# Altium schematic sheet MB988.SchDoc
size A3; Revision: B.2
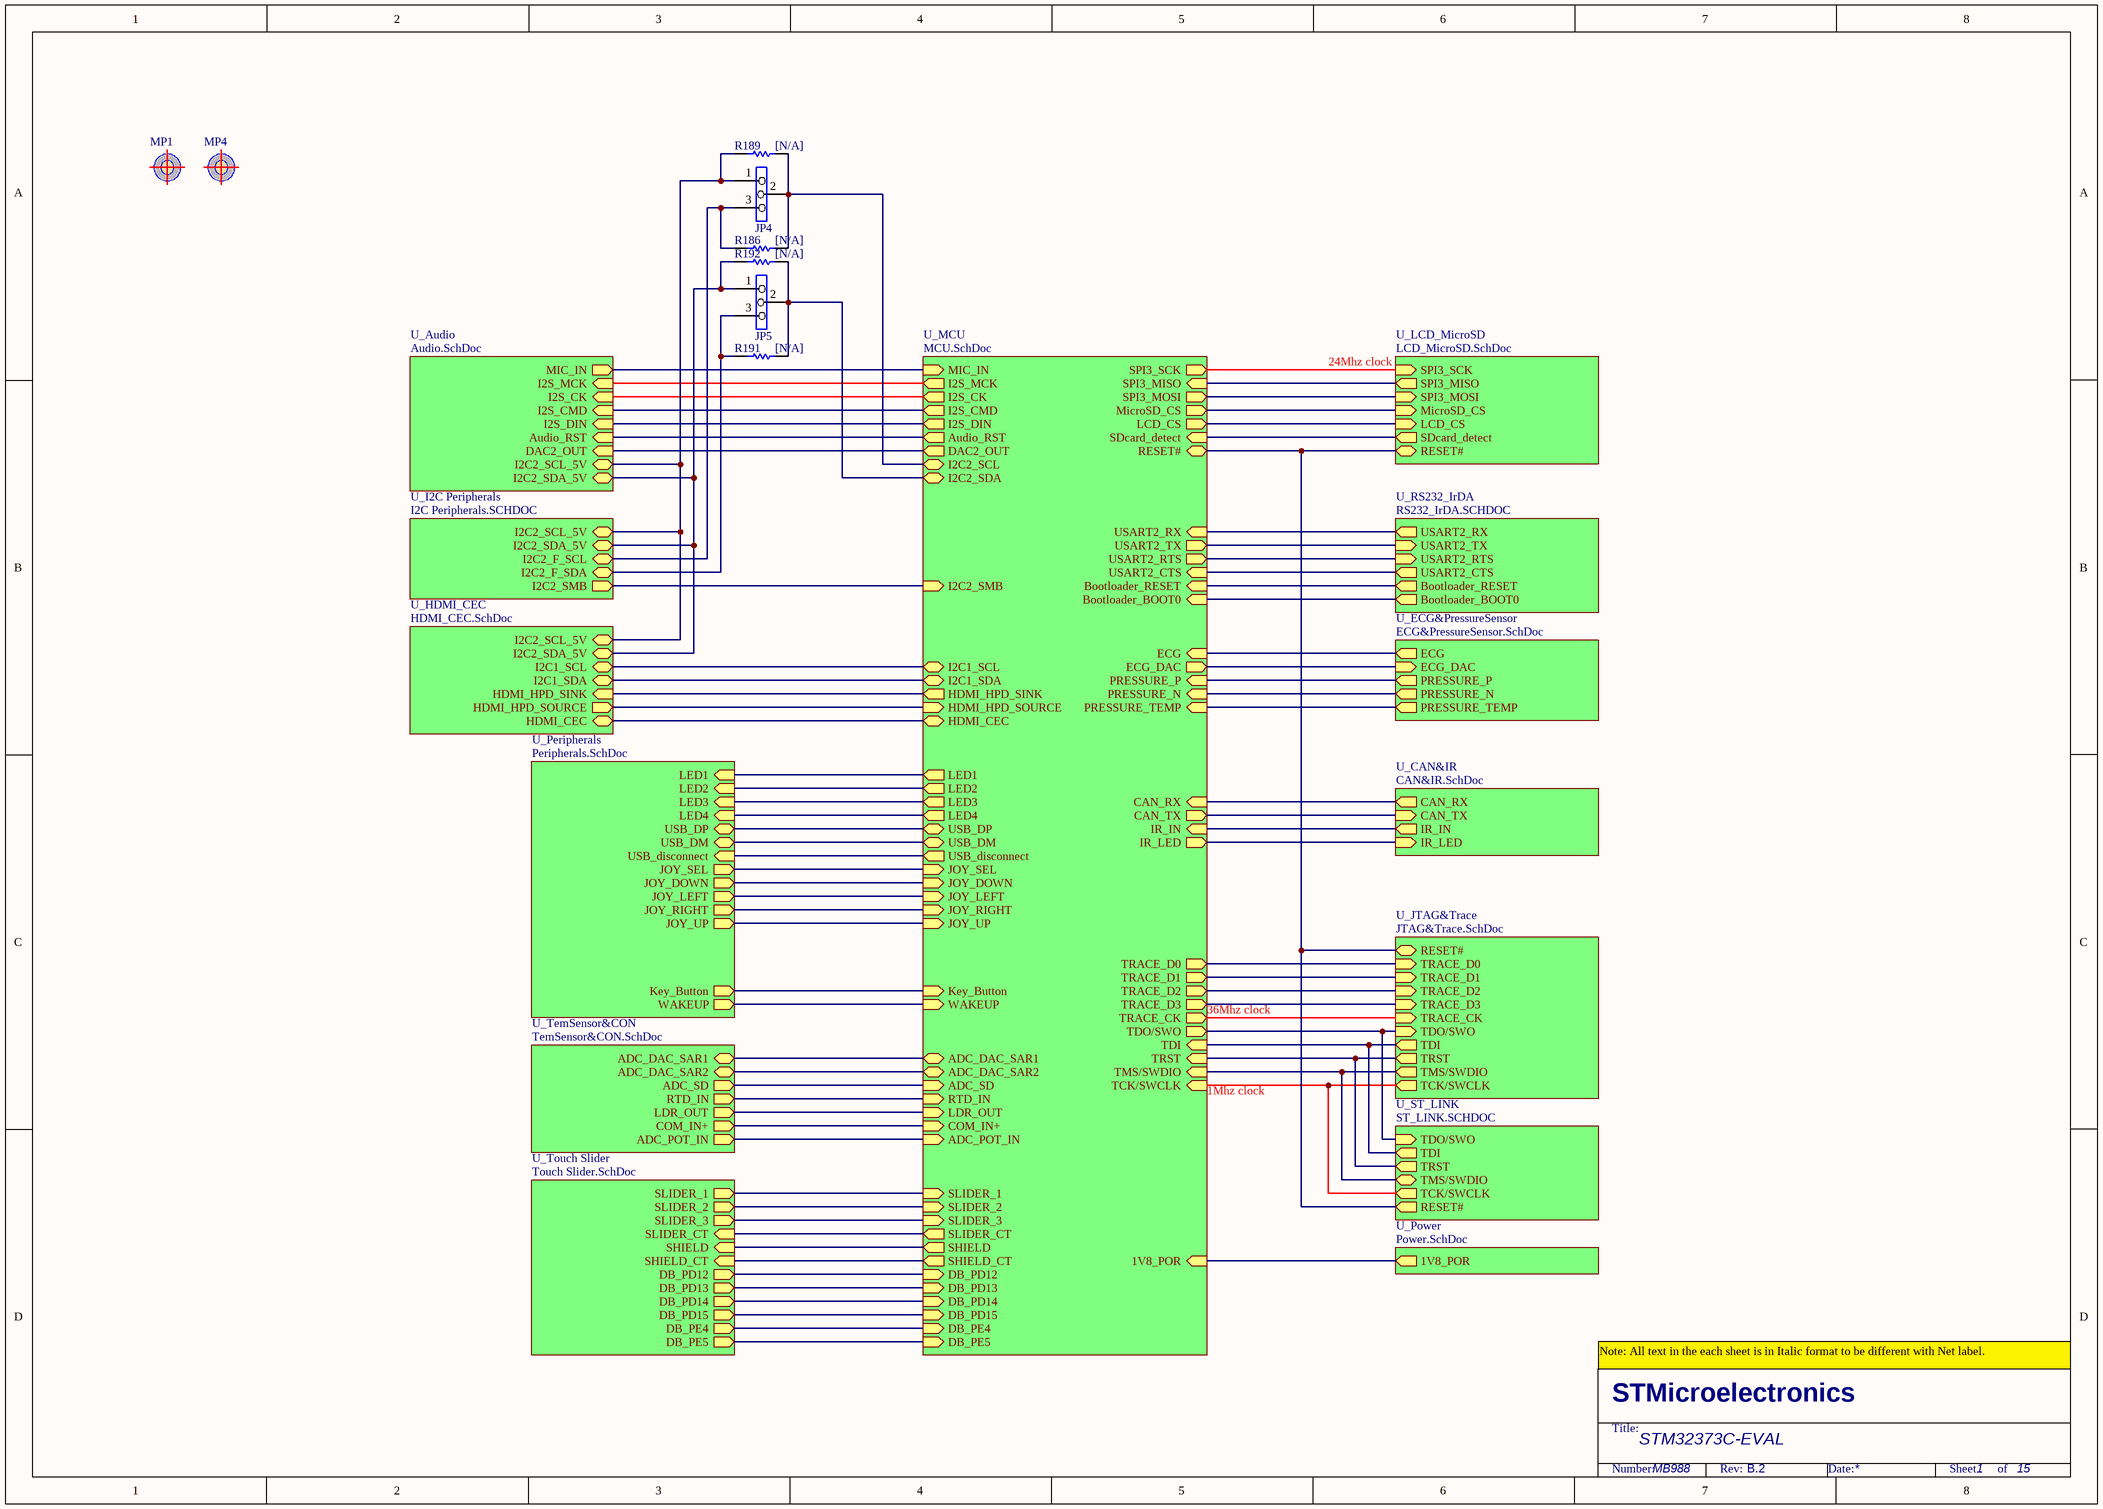
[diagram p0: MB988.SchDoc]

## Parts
JP4  (no value)  [SIP3]
JP5  (no value)  [SIP3]
MP1  (no value)  [markpoint_1.0]
MP4  (no value)  [markpoint_1.0]
R186  [N/A]  [0603R]
R189  [N/A]  [0603R]
R191  [N/A]  [0603R]
R192  [N/A]  [0603R]

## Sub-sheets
U_Audio = Audio.SchDoc: I2S_CMD (in), I2S_DIN (in), I2S_CK (in), I2C2_SCL_5V (bidir), I2C2_SDA_5V (bidir), Audio_RST (in), I2S_MCK (in), DAC2_OUT (in), MIC_IN (out)
U_CAN&IR = CAN&IR.SchDoc: CAN_TX (in), CAN_RX (out), IR_LED (in), IR_IN (out)
U_ECG&PressureSensor = ECG&PressureSensor.SchDoc: ECG (out), PRESSURE_P (out), PRESSURE_N (out), ECG_DAC (in), PRESSURE_TEMP (out)
U_HDMI_CEC = HDMI_CEC.SchDoc: HDMI_HPD_SINK (in), I2C2_SDA_5V (bidir), I2C2_SCL_5V (bidir), HDMI_CEC (bidir), HDMI_HPD_SOURCE (out), I2C1_SCL (bidir), I2C1_SDA (bidir)
U_I2C Peripherals = I2C Peripherals.SCHDOC: I2C2_SCL_5V (bidir), I2C2_SDA_5V (bidir), I2C2_SMB (out), I2C2_F_SDA (bidir), I2C2_F_SCL (bidir)
U_JTAG&Trace = JTAG&Trace.SchDoc: TDI (out), RESET# (bidir), TRACE_D3 (in), TRACE_D2 (in), TRACE_D1 (in), TRACE_D0 (in), TRACE_CK (in), TRST (out), TMS/SWDIO (out), TCK/SWCLK (out), TDO/SWO (in)
U_LCD_MicroSD = LCD_MicroSD.SchDoc: MicroSD_CS (in), SPI3_SCK (in), SPI3_MOSI (in), LCD_CS (in), SPI3_MISO (out), SDcard_detect (out), RESET# (bidir)
U_MCU = MCU.SchDoc: WAKEUP (in), HDMI_HPD_SOURCE (in), SLIDER_3 (in), ADC_DAC_SAR2 (bidir), USB_DM (bidir), I2C2_SCL (bidir), I2C2_SDA (bidir), TMS/SWDIO (in), TCK/SWCLK (in), TDI (in), MIC_IN (in), COM_IN+ (in), TDO/SWO (out), TRST (in), IR_IN (in), HDMI_CEC (bidir), IR_LED (out), RESET# (bidir), LDR_OUT (in), SLIDER_2 (in), SLIDER_1 (in), USART2_RX (in), USART2_TX (out), USART2_RTS (out), USART2_CTS (in), ECG (in), ADC_SD (in), PRESSURE_N (in), PRESSURE_P (in), SPI3_MOSI (out), SPI3_MISO (in), SPI3_SCK (out), LED4 (out), LED3 (out), LED1 (out), I2S_MCK (out), I2S_CK (out), I2S_CMD (out), LED2 (out), Bootloader_BOOT0 (in), Bootloader_RESET (in), ADC_DAC_SAR1 (bidir), I2S_DIN (out), I2C2_SMB (in), USB_DP (bidir), CAN_RX (in), CAN_TX (out), SLIDER_CT (out), MicroSD_CS (out), TRACE_D0 (out), TRACE_D1 (out), Key_Button (in), JOY_SEL (in), RTD_IN (in), PRESSURE_TEMP (in), JOY_DOWN (in), JOY_LEFT (in), JOY_UP (in), JOY_RIGHT (in), DAC2_OUT (out), TRACE_CK (out), LCD_CS (out), SHIELD (out), TRACE_D2 (out), SHIELD_CT (out), TRACE_D3 (out), HDMI_HPD_SINK (out), Audio_RST (out), SDcard_detect (in), ECG_DAC (out), ADC_POT_IN (in), DB_PD14 (in), DB_PD13 (in), DB_PD12 (in), DB_PD15 (in), 1V8_POR (in), USB_disconnect (out), I2C1_SCL (bidir), I2C1_SDA (bidir), DB_PE4 (in), DB_PE5 (in)
U_Peripherals = Peripherals.SchDoc: LED4 (in), LED3 (in), LED1 (in), LED2 (in), JOY_SEL (out), JOY_DOWN (out), JOY_LEFT (out), JOY_RIGHT (out), JOY_UP (out), USB_DM (bidir), USB_DP (bidir), WAKEUP (out), Key_Button (out), USB_disconnect (in)
U_Power = Power.SchDoc: 1V8_POR (out)
U_RS232_IrDA = RS232_IrDA.SCHDOC: USART2_TX (in), USART2_CTS (out), Bootloader_RESET (out), Bootloader_BOOT0 (out), USART2_RX (out), USART2_RTS (in)
U_ST_LINK = ST_LINK.SCHDOC: TDI (out), TRST (out), TMS/SWDIO (bidir), TCK/SWCLK (out), TDO/SWO (in), RESET# (out)
U_TemSensor&CON = TemSensor&CON.SchDoc: RTD_IN (out), LDR_OUT (out), COM_IN+ (out), ADC_POT_IN (out), ADC_DAC_SAR1 (bidir), ADC_SD (out), ADC_DAC_SAR2 (bidir)
U_Touch Slider = Touch Slider.SchDoc: SLIDER_2 (out), SLIDER_3 (out), SHIELD (in), SHIELD_CT (in), SLIDER_1 (out), DB_PD14 (out), DB_PD13 (out), DB_PD12 (out), SLIDER_CT (in), DB_PD15 (out), DB_PE4 (out), DB_PE5 (out)

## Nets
NetJP4_1: JP4.1 R189.2 ; sheet U_Audio/I2C2_SCL_5V, sheet U_I2C Peripherals/I2C2_SCL_5V, sheet U_HDMI_CEC/I2C2_SCL_5V
NetJP4_2: JP4.2 R186.1 R189.1 ; sheet U_MCU/I2C2_SCL
NetJP4_3: JP4.3 R186.2 ; sheet U_I2C Peripherals/I2C2_F_SCL
NetJP5_1: JP5.1 R192.2 ; sheet U_Audio/I2C2_SDA_5V, sheet U_I2C Peripherals/I2C2_SDA_5V, sheet U_HDMI_CEC/I2C2_SDA_5V
NetJP5_2: JP5.2 R191.1 R192.1 ; sheet U_MCU/I2C2_SDA
NetJP5_3: JP5.3 R191.2 ; sheet U_I2C Peripherals/I2C2_F_SDA
(unnamed): sheet U_MCU/WAKEUP, sheet U_Peripherals/WAKEUP
(unnamed): sheet U_MCU/HDMI_HPD_SOURCE, sheet U_HDMI_CEC/HDMI_HPD_SOURCE  [a separate net that carries the same name]
(unnamed): sheet U_MCU/SLIDER_3, sheet U_Touch Slider/SLIDER_3  [a separate net that carries the same name]
(unnamed): sheet U_MCU/ADC_DAC_SAR2, sheet U_TemSensor&CON/ADC_DAC_SAR2  [a separate net that carries the same name]
(unnamed): sheet U_MCU/USB_DM, sheet U_Peripherals/USB_DM  [a separate net that carries the same name]
(unnamed): sheet U_MCU/TMS/SWDIO, sheet U_JTAG&Trace/TMS/SWDIO, sheet U_ST_LINK/TMS/SWDIO  [a separate net that carries the same name]
(unnamed): sheet U_MCU/TCK/SWCLK, sheet U_JTAG&Trace/TCK/SWCLK, sheet U_ST_LINK/TCK/SWCLK  [a separate net that carries the same name]
(unnamed): sheet U_MCU/TDI, sheet U_JTAG&Trace/TDI, sheet U_ST_LINK/TDI  [a separate net that carries the same name]
(unnamed): sheet U_MCU/MIC_IN, sheet U_Audio/MIC_IN  [a separate net that carries the same name]
(unnamed): sheet U_MCU/COM_IN+, sheet U_TemSensor&CON/COM_IN+  [a separate net that carries the same name]
(unnamed): sheet U_MCU/TDO/SWO, sheet U_JTAG&Trace/TDO/SWO, sheet U_ST_LINK/TDO/SWO  [a separate net that carries the same name]
(unnamed): sheet U_MCU/TRST, sheet U_JTAG&Trace/TRST, sheet U_ST_LINK/TRST  [a separate net that carries the same name]
(unnamed): sheet U_MCU/IR_IN, sheet U_CAN&IR/IR_IN  [a separate net that carries the same name]
(unnamed): sheet U_MCU/HDMI_CEC, sheet U_HDMI_CEC/HDMI_CEC  [a separate net that carries the same name]
(unnamed): sheet U_MCU/IR_LED, sheet U_CAN&IR/IR_LED  [a separate net that carries the same name]
(unnamed): sheet U_MCU/RESET#, sheet U_JTAG&Trace/RESET#, sheet U_ST_LINK/RESET#, sheet U_LCD_MicroSD/RESET#  [a separate net that carries the same name]
(unnamed): sheet U_MCU/LDR_OUT, sheet U_TemSensor&CON/LDR_OUT  [a separate net that carries the same name]
(unnamed): sheet U_MCU/SLIDER_2, sheet U_Touch Slider/SLIDER_2  [a separate net that carries the same name]
(unnamed): sheet U_MCU/SLIDER_1, sheet U_Touch Slider/SLIDER_1  [a separate net that carries the same name]
(unnamed): sheet U_MCU/USART2_RX, sheet U_RS232_IrDA/USART2_RX  [a separate net that carries the same name]
(unnamed): sheet U_MCU/USART2_TX, sheet U_RS232_IrDA/USART2_TX  [a separate net that carries the same name]
(unnamed): sheet U_MCU/USART2_RTS, sheet U_RS232_IrDA/USART2_RTS  [a separate net that carries the same name]
(unnamed): sheet U_MCU/USART2_CTS, sheet U_RS232_IrDA/USART2_CTS  [a separate net that carries the same name]
(unnamed): sheet U_MCU/ECG, sheet U_ECG&PressureSensor/ECG  [a separate net that carries the same name]
(unnamed): sheet U_MCU/ADC_SD, sheet U_TemSensor&CON/ADC_SD  [a separate net that carries the same name]
(unnamed): sheet U_MCU/PRESSURE_N, sheet U_ECG&PressureSensor/PRESSURE_N  [a separate net that carries the same name]
(unnamed): sheet U_MCU/PRESSURE_P, sheet U_ECG&PressureSensor/PRESSURE_P  [a separate net that carries the same name]
(unnamed): sheet U_MCU/SPI3_MOSI, sheet U_LCD_MicroSD/SPI3_MOSI  [a separate net that carries the same name]
(unnamed): sheet U_MCU/SPI3_MISO, sheet U_LCD_MicroSD/SPI3_MISO  [a separate net that carries the same name]
(unnamed): sheet U_MCU/SPI3_SCK, sheet U_LCD_MicroSD/SPI3_SCK  [a separate net that carries the same name]
(unnamed): sheet U_MCU/LED4, sheet U_Peripherals/LED4  [a separate net that carries the same name]
(unnamed): sheet U_MCU/LED3, sheet U_Peripherals/LED3  [a separate net that carries the same name]
(unnamed): sheet U_MCU/LED1, sheet U_Peripherals/LED1  [a separate net that carries the same name]
(unnamed): sheet U_MCU/I2S_MCK, sheet U_Audio/I2S_MCK  [a separate net that carries the same name]
(unnamed): sheet U_MCU/I2S_CK, sheet U_Audio/I2S_CK  [a separate net that carries the same name]
(unnamed): sheet U_MCU/I2S_CMD, sheet U_Audio/I2S_CMD  [a separate net that carries the same name]
(unnamed): sheet U_MCU/LED2, sheet U_Peripherals/LED2  [a separate net that carries the same name]
(unnamed): sheet U_MCU/Bootloader_BOOT0, sheet U_RS232_IrDA/Bootloader_BOOT0  [a separate net that carries the same name]
(unnamed): sheet U_MCU/Bootloader_RESET, sheet U_RS232_IrDA/Bootloader_RESET  [a separate net that carries the same name]
(unnamed): sheet U_MCU/ADC_DAC_SAR1, sheet U_TemSensor&CON/ADC_DAC_SAR1  [a separate net that carries the same name]
(unnamed): sheet U_MCU/I2S_DIN, sheet U_Audio/I2S_DIN  [a separate net that carries the same name]
(unnamed): sheet U_MCU/I2C2_SMB, sheet U_I2C Peripherals/I2C2_SMB  [a separate net that carries the same name]
(unnamed): sheet U_MCU/USB_DP, sheet U_Peripherals/USB_DP  [a separate net that carries the same name]
(unnamed): sheet U_MCU/CAN_RX, sheet U_CAN&IR/CAN_RX  [a separate net that carries the same name]
(unnamed): sheet U_MCU/CAN_TX, sheet U_CAN&IR/CAN_TX  [a separate net that carries the same name]
(unnamed): sheet U_MCU/SLIDER_CT, sheet U_Touch Slider/SLIDER_CT  [a separate net that carries the same name]
(unnamed): sheet U_MCU/MicroSD_CS, sheet U_LCD_MicroSD/MicroSD_CS  [a separate net that carries the same name]
(unnamed): sheet U_MCU/TRACE_D0, sheet U_JTAG&Trace/TRACE_D0  [a separate net that carries the same name]
(unnamed): sheet U_MCU/TRACE_D1, sheet U_JTAG&Trace/TRACE_D1  [a separate net that carries the same name]
(unnamed): sheet U_MCU/Key_Button, sheet U_Peripherals/Key_Button  [a separate net that carries the same name]
(unnamed): sheet U_MCU/JOY_SEL, sheet U_Peripherals/JOY_SEL  [a separate net that carries the same name]
(unnamed): sheet U_MCU/RTD_IN, sheet U_TemSensor&CON/RTD_IN  [a separate net that carries the same name]
(unnamed): sheet U_MCU/PRESSURE_TEMP, sheet U_ECG&PressureSensor/PRESSURE_TEMP  [a separate net that carries the same name]
(unnamed): sheet U_MCU/JOY_DOWN, sheet U_Peripherals/JOY_DOWN  [a separate net that carries the same name]
(unnamed): sheet U_MCU/JOY_LEFT, sheet U_Peripherals/JOY_LEFT  [a separate net that carries the same name]
(unnamed): sheet U_MCU/JOY_UP, sheet U_Peripherals/JOY_UP  [a separate net that carries the same name]
(unnamed): sheet U_MCU/JOY_RIGHT, sheet U_Peripherals/JOY_RIGHT  [a separate net that carries the same name]
(unnamed): sheet U_MCU/DAC2_OUT, sheet U_Audio/DAC2_OUT  [a separate net that carries the same name]
(unnamed): sheet U_MCU/TRACE_CK, sheet U_JTAG&Trace/TRACE_CK  [a separate net that carries the same name]
(unnamed): sheet U_MCU/LCD_CS, sheet U_LCD_MicroSD/LCD_CS  [a separate net that carries the same name]
(unnamed): sheet U_MCU/SHIELD, sheet U_Touch Slider/SHIELD  [a separate net that carries the same name]
(unnamed): sheet U_MCU/TRACE_D2, sheet U_JTAG&Trace/TRACE_D2  [a separate net that carries the same name]
(unnamed): sheet U_MCU/SHIELD_CT, sheet U_Touch Slider/SHIELD_CT  [a separate net that carries the same name]
(unnamed): sheet U_MCU/TRACE_D3, sheet U_JTAG&Trace/TRACE_D3  [a separate net that carries the same name]
(unnamed): sheet U_MCU/HDMI_HPD_SINK, sheet U_HDMI_CEC/HDMI_HPD_SINK  [a separate net that carries the same name]
(unnamed): sheet U_MCU/Audio_RST, sheet U_Audio/Audio_RST  [a separate net that carries the same name]
(unnamed): sheet U_MCU/SDcard_detect, sheet U_LCD_MicroSD/SDcard_detect  [a separate net that carries the same name]
(unnamed): sheet U_MCU/ECG_DAC, sheet U_ECG&PressureSensor/ECG_DAC  [a separate net that carries the same name]
(unnamed): sheet U_MCU/ADC_POT_IN, sheet U_TemSensor&CON/ADC_POT_IN  [a separate net that carries the same name]
(unnamed): sheet U_MCU/DB_PD14, sheet U_Touch Slider/DB_PD14  [a separate net that carries the same name]
(unnamed): sheet U_MCU/DB_PD13, sheet U_Touch Slider/DB_PD13  [a separate net that carries the same name]
(unnamed): sheet U_MCU/DB_PD12, sheet U_Touch Slider/DB_PD12  [a separate net that carries the same name]
(unnamed): sheet U_MCU/DB_PD15, sheet U_Touch Slider/DB_PD15  [a separate net that carries the same name]
(unnamed): sheet U_MCU/1V8_POR, sheet U_Power/1V8_POR  [a separate net that carries the same name]
(unnamed): sheet U_MCU/USB_disconnect, sheet U_Peripherals/USB_disconnect  [a separate net that carries the same name]
(unnamed): sheet U_MCU/I2C1_SCL, sheet U_HDMI_CEC/I2C1_SCL  [a separate net that carries the same name]
(unnamed): sheet U_MCU/I2C1_SDA, sheet U_HDMI_CEC/I2C1_SDA  [a separate net that carries the same name]
(unnamed): sheet U_MCU/DB_PE4, sheet U_Touch Slider/DB_PE4  [a separate net that carries the same name]
(unnamed): sheet U_MCU/DB_PE5, sheet U_Touch Slider/DB_PE5  [a separate net that carries the same name]

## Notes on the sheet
- 24Mhz clock
- 36Mhz clock
- 1Mhz clock
- Note: All text in the each sheet is in Italic format to be different with Net label.
- STM32373C-EVAL
- MB988
- 1
- 15

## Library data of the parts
JP4 JP5 = Jumper3
MP1 MP4 = MARKPOINT
R186 R189 R191 R192 = Res1: Resistor; Value: 1K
